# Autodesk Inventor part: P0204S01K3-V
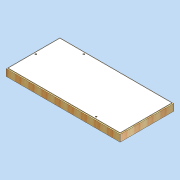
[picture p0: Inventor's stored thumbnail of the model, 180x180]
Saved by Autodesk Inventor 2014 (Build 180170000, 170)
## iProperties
Created: 2011-04
Part Number: P0204S01K3-V
Document SubType Name: Modeling
Designer: david.appleford
Density: 0.222024 g/cm^3
Description: 0.5w x 1w 01 Panel - 3 Locks
Mass: 11000 g
Surface Area: 15198.7 cm^2
Volume: 49544.2 cm^3
Cost Center: £55.00
Material: Generic
Appearance: Wood (Pine)
Justset: False
Title: 0.5w x 1w 01 Panel - 3 Locks
Author: david.appleford
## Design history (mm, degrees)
sketch "Sketch1"
  geometry: L1 (0, 0)-(1220, 0); L2 (1220, 0)-(1220, 610); L3 (1220, 610)-(0, 610); L4 (0, 610)-(0, 0); L5 (34, 576)-(1186, 576); L6 (1186, 576)-(1186, 34); L7 (1186, 34)-(34, 34); L8 (34, 34)-(34, 576)
  constraints: 16 end point, 4 parallel, 2 perpendicular, 1 horizontal, 3 other
  dimensions: "d0" = 1220 distance between parallel lines of L2 L4 (= w); "d1" = 610 distance between parallel lines of L1 L3 (= 0.5 x w); "d2" = 34 distance between parallel lines of L5 L3 (= 0.5 x t)
extrude "Extrusion1" new body sketch "Sketch1" distance "d3" = 68 (= t); taper "d4" = 0 deg
sketch "Sketch2"
  geometry: L1 (1186, 576)-(1186, 34) reference; L2 (34, 576)-(1186, 576) reference; L3 (34, 34)-(34, 576) reference; L4 (1186, 34)-(34, 34) reference; L5 (1176, 566)-(1176, 44); L6 (1176, 44)-(44, 44); L7 (44, 44)-(44, 566); L8 (44, 566)-(1176, 566); 1 further point
  constraints: 8 end point, 3 other
  dimensions: "d5" = 10 distance between parallel lines of L8 L2
extrude "Extrusion2" join sketch "Sketch2" distance "d6" = 6 (= sw); taper "d7" = 0 deg
sketch "Sketch3"
  geometry: L1 (-44, 566)-(-1176, 566) reference; L2 (-1176, 566)-(-1176, 44) reference; L3 (-44, 44)-(-44, 566) reference; L4 (-1176, 44)-(-44, 44) reference; 1 further point
extrude "Extrusion3" join sketch "Sketch3" distance "d8" = 6 (= sw); taper "d9" = 0 deg
sketch "Sketch4"
  geometry: L1 (34, 576)-(1186, 576) reference; L2 (1186, 576)-(1186, 34) reference; L3 (1186, 34)-(34, 34) reference; L4 (34, 34)-(34, 576) reference; 5 further points
  constraints: 1 horizontal alignment
  dimensions: "d10" = 28 distance from line of point (305, 548) L1 (= k); "d12" = 28 distance from line of L3 point (915, 62) (= k); "d13" = 28 distance from line of point (62, 305) L4 (= k); "d14" = 305 horizontal distance of point (305, 548) point (0, 0) (= 0.25 x w); "d15" = 610 horizontal distance of point (915, 62) point (305, 548) (= 0.5 x w); "d16" = 305 vertical distance of point (62, 305) point (0, 0) (= 0.25 x w); "d29" = 28 distance from line of L2 point (1158, 305) (= d13)
hole "Hole1" sketch "Sketch4" at (305, 548), (62, 305), (915, 62) diameter "d22" = 16.3; stored, may be unused: countersink angle "d26" = 90 deg, drill point angle "d28" = 118 deg; dims "d23" = 6, "d24" = 4, "d25" = 2, "d27" = 6
body "Solid1"
node "Projected Loop1"
other parameters: "w" = 1220 [user parameter; used in 5 equation terms], "t" = 68 [user parameter; used in 2 equation terms], "e" = 16 [user parameter], "sw" = 6 [user parameter; used in 2 equation terms], "sc" = 9 [user parameter], "sf" = 12 [user parameter], "k" = 28 [user parameter; used in 3 equation terms], "hd" = 12 [user parameter]
